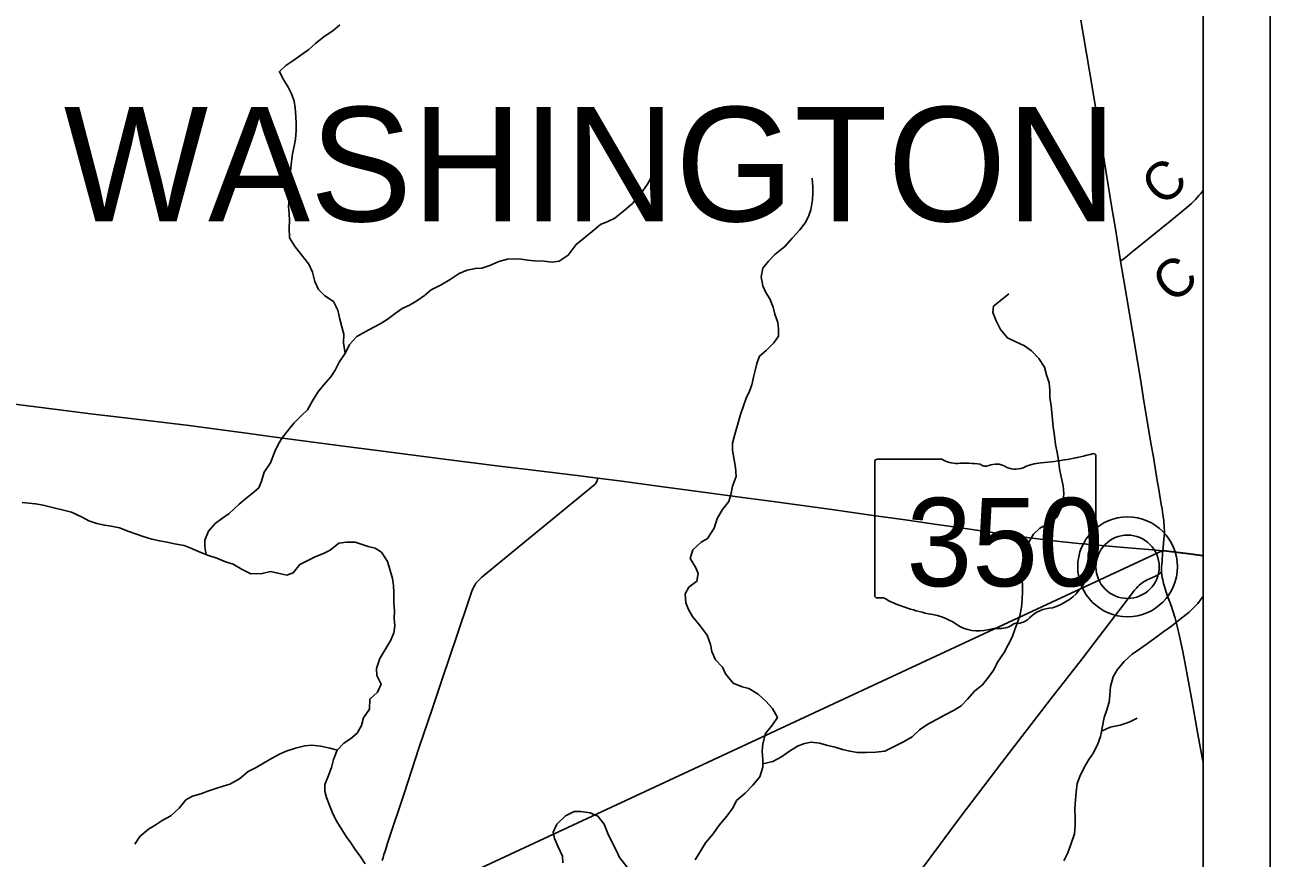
# Model space of a CAD drawing. Extents: x 0 to 34, y 0 to 22.
# Drawn here: x 7.143 to 9, y 16.125 to 17.368 of the extents above; entities that cross this region are included whole.
import ezdxf

# ---------------------------------------------------------------- set-up
doc = ezdxf.new("R2010")
doc.units = 0
for name, color, linetype in [('GM_X_County_Road', 7, 'Continuous'), ('GM_X_County_Road_Text', 7, 'Continuous'), ('GM_X_Minor_River', 7, 'Continuous'), ('GM_X_State_Location', 7, 'Continuous'), ('GM_X_State_Route', 7, 'Continuous'), ('GM_X_State_Shield', 7, 'Continuous'), ('GM_X_Township_Road', 7, 'Continuous'), ('GM_X_Township_Text', 7, 'Continuous'), ('GM_X_Unincorporated', 7, 'Continuous'), ('GM_X_Unincorporated_Location', 7, 'Continuous'), ('SH_Data', 7, 'Continuous')]:
    doc.layers.add(name, color=color, linetype=linetype)

msp = doc.modelspace()

# ---------------------------------------------------------------- linework, layer by layer
at = {"layer": 'GM_X_County_Road'}
for points in [[(8.7771, 17.0151), (8.7843, 17.021), (8.7939, 17.0288), (8.8503, 17.0747), (8.8759, 17.0954), (8.8828, 17.1015), (8.8858, 17.1044), (8.8886, 17.1071), (8.8912, 17.1101), (8.8939, 17.1131), (8.8961, 17.1159), (8.8985, 17.1189), (8.9, 17.121)], [(8.4696, 16.0943), (8.5071, 16.1446), (8.5308, 16.1765), (8.5465, 16.1973), (8.6, 16.2675), (8.673, 16.3626), (8.7196, 16.4224), (8.745, 16.4554), (8.7808, 16.5023), (8.7963, 16.5225), (8.798, 16.5245), (8.8007, 16.5276), (8.8028, 16.53), (8.805, 16.532), (8.8068, 16.5335), (8.8087, 16.5351), (8.8105, 16.5364), (8.8122, 16.5375), (8.8143, 16.5388), (8.8165, 16.5399), (8.8282, 16.545), (8.831, 16.5464), (8.8334, 16.548), (8.8383, 16.5513)]]:
    msp.add_lwpolyline(points, dxfattribs=at)
at = {"layer": 'GM_X_Minor_River'}
for points in [[(7.6207, 16.8777), (7.6184, 16.8933), (7.619, 16.9066), (7.6161, 16.9172), (7.6132, 16.929), (7.6099, 16.942), (7.6033, 16.955), (7.5905, 16.9635), (7.5811, 16.9731), (7.5759, 16.9849), (7.572, 16.999), (7.5668, 17.0109), (7.5556, 17.025), (7.5463, 17.0369), (7.5377, 17.0503), (7.5375, 17.0651), (7.538, 17.0754), (7.5374, 17.0864), (7.5364, 17.0963), (7.5374, 17.1099), (7.5387, 17.1266), (7.5393, 17.1399), (7.5394, 17.1498), (7.5408, 17.1642), (7.5424, 17.1752), (7.5449, 17.1869), (7.5469, 17.1975), (7.5478, 17.2104), (7.548, 17.2206), (7.5474, 17.2309), (7.5464, 17.2438), (7.545, 17.2541), (7.5413, 17.264), (7.5358, 17.2747), (7.5276, 17.2889), (7.5228, 17.2984), (7.5324, 17.307), (7.5428, 17.3141), (7.5547, 17.3227), (7.5669, 17.3312), (7.5766, 17.3398), (7.5896, 17.3503), (7.6026, 17.3589), (7.613, 17.3678)], [(7.4138, 16.5776), (7.4115, 16.5892), (7.4116, 16.5991), (7.4171, 16.6127), (7.4271, 16.6243), (7.4367, 16.631), (7.4482, 16.6392), (7.4628, 16.6531), (7.4724, 16.6609), (7.4824, 16.6688), (7.492, 16.6774), (7.4964, 16.6872), (7.5003, 16.7004), (7.5096, 16.7144), (7.5163, 16.7314), (7.521, 16.7419), (7.5268, 16.7517), (7.5365, 16.7638), (7.545, 16.7743), (7.5554, 16.7848), (7.565, 16.7934), (7.572, 16.8069), (7.5802, 16.8197), (7.5887, 16.8306), (7.5995, 16.843), (7.6061, 16.8528), (7.6119, 16.8645), (7.6212, 16.8784), (7.6275, 16.8909), (7.6383, 16.9029), (7.6505, 16.9099), (7.6635, 16.917), (7.6731, 16.9218), (7.6834, 16.9281), (7.6957, 16.9371), (7.7057, 16.9445), (7.7168, 16.9497), (7.7279, 16.956), (7.7394, 16.9642), (7.7494, 16.9724), (7.7643, 16.9798), (7.7773, 16.988), (7.7911, 16.9969), (7.8029, 17.0021), (7.8151, 17.0046), (7.8246, 17.0049), (7.8365, 17.0089), (7.8498, 17.0148), (7.8632, 17.0184), (7.8734, 17.019), (7.8833, 17.0182), (7.8935, 17.0169), (7.903, 17.016), (7.9174, 17.0151), (7.9296, 17.0138), (7.9399, 17.0155), (7.9533, 17.0245), (7.9653, 17.0402), (7.9756, 17.0488), (7.9891, 17.0597), (8.0017, 17.0698), (8.0128, 17.0746), (8.0228, 17.0794), (8.0366, 17.0902), (8.0493, 17.1014), (8.0612, 17.1153), (8.0717, 17.13), (8.0794, 17.1435)], [(8.1502, 16.4715), (8.1386, 16.4853), (8.1326, 16.496), (8.129, 16.5059), (8.128, 16.5192), (8.1335, 16.529), (8.1454, 16.538), (8.1474, 16.5493), (8.1434, 16.5589), (8.1352, 16.5719), (8.1395, 16.5847), (8.1515, 16.596), (8.161, 16.6019), (8.1711, 16.617), (8.1755, 16.6317), (8.1836, 16.6449), (8.1929, 16.6569), (8.1961, 16.6668), (8.1985, 16.6796), (8.2037, 16.694), (8.2031, 16.7077), (8.201, 16.7191), (8.1985, 16.7335), (8.1983, 16.7438), (8.2023, 16.7589), (8.207, 16.7741), (8.2102, 16.7865), (8.2142, 16.7983), (8.2189, 16.8111), (8.2236, 16.8213), (8.2275, 16.8311), (8.23, 16.8421), (8.232, 16.8523), (8.2348, 16.8629), (8.2388, 16.8735), (8.2484, 16.8821), (8.2603, 16.8933), (8.2669, 16.9035), (8.267, 16.9145), (8.266, 16.924), (8.2616, 16.9362), (8.2591, 16.9465), (8.254, 16.9591), (8.248, 16.9686), (8.2436, 16.9786), (8.2411, 16.9919), (8.2436, 17.0048), (8.2521, 17.0153), (8.2617, 17.0254), (8.2767, 17.037), (8.2875, 17.0497), (8.2986, 17.0621), (8.3068, 17.0723), (8.3118, 17.0821), (8.3154, 17.0919), (8.3175, 17.1067), (8.3184, 17.1169), (8.3181, 17.1264), (8.3172, 17.1393)], [(8.2439, 16.2657), (8.2587, 16.2693), (8.2717, 16.2759), (8.2836, 16.2845), (8.2955, 16.292), (8.3058, 16.296), (8.3157, 16.2981), (8.3282, 16.2965), (8.3407, 16.2929), (8.3517, 16.2905), (8.3627, 16.2869), (8.3733, 16.2845), (8.3846, 16.2824), (8.3979, 16.2827), (8.412, 16.2829), (8.4257, 16.2846), (8.4387, 16.2909), (8.4532, 16.2983), (8.4662, 16.3061), (8.4774, 16.3165), (8.4896, 16.3247), (8.5026, 16.3318), (8.5145, 16.3381), (8.529, 16.3459), (8.5394, 16.3522), (8.5486, 16.3619), (8.5598, 16.3747), (8.571, 16.3837), (8.5802, 16.3949), (8.588, 16.4058), (8.5938, 16.4172), (8.6035, 16.4318), (8.6152, 16.4545), (8.6195, 16.4658), (8.6231, 16.4756), (8.6267, 16.4866), (8.6295, 16.4991), (8.6304, 16.5104), (8.631, 16.5237), (8.6307, 16.5332), (8.6297, 16.5427), (8.6298, 16.5541), (8.6304, 16.564), (8.6336, 16.5783), (8.6387, 16.5938), (8.6473, 16.6082), (8.6569, 16.6171), (8.6707, 16.6246), (8.6826, 16.6339), (8.6892, 16.6479), (8.6916, 16.6584), (8.6925, 16.6687), (8.6915, 16.6801), (8.6887, 16.6938), (8.6862, 16.7056), (8.6845, 16.7185), (8.6823, 16.7299), (8.6802, 16.7421), (8.6785, 16.7547), (8.6768, 16.7683), (8.6758, 16.7786), (8.6748, 16.7892), (8.6734, 16.7999), (8.6717, 16.8117), (8.6714, 16.8227), (8.6704, 16.8337), (8.6668, 16.8459), (8.6635, 16.857), (8.6554, 16.8704), (8.6445, 16.8815), (8.634, 16.8889), (8.6208, 16.8951), (8.6083, 16.901), (8.5978, 16.9132), (8.5916, 16.9262), (8.5864, 16.9388), (8.5877, 16.9483), (8.5973, 16.9561), (8.6103, 16.9666)], [(7.5203, 16.5502), (7.5097, 16.5523), (7.4972, 16.5494), (7.4804, 16.5492), (7.4672, 16.5555), (7.454, 16.5636), (7.4427, 16.5668), (7.4295, 16.5723), (7.4174, 16.5763), (7.403, 16.5818), (7.3932, 16.5861), (7.3811, 16.5915), (7.3667, 16.5936), (7.3554, 16.5964), (7.344, 16.5981), (7.3326, 16.6005), (7.3198, 16.6045), (7.3099, 16.6084), (7.2982, 16.6123), (7.2846, 16.6174), (7.2721, 16.6199), (7.2619, 16.6215), (7.2509, 16.624), (7.2388, 16.6283), (7.2286, 16.6337), (7.2131, 16.6408), (7.1991, 16.6444), (7.1866, 16.6476), (7.1707, 16.6512), (7.159, 16.6536), (7.1495, 16.6545), (7.1393, 16.6554)], [(7.6505, 16.1166), (7.6442, 16.1265), (7.636, 16.138), (7.6296, 16.1476), (7.6225, 16.1572), (7.6136, 16.1717), (7.6077, 16.1813), (7.6021, 16.1924), (7.5981, 16.2023), (7.5933, 16.2153), (7.5908, 16.2248), (7.5905, 16.235), (7.5949, 16.246), (7.6004, 16.26), (7.6036, 16.2721), (7.6091, 16.286), (7.6191, 16.2965), (7.6287, 16.3029), (7.639, 16.3115), (7.6453, 16.3228), (7.6485, 16.3341), (7.6574, 16.3473), (7.6576, 16.3621), (7.6691, 16.3726), (7.6746, 16.3846), (7.6683, 16.3976), (7.6677, 16.4079), (7.6724, 16.4226), (7.6814, 16.4377), (7.6888, 16.4501), (7.6935, 16.4611), (7.6951, 16.4717), (7.6941, 16.4823), (7.6943, 16.4937), (7.6933, 16.5059), (7.6935, 16.5211), (7.6929, 16.5317), (7.6915, 16.542), (7.6868, 16.5576), (7.6839, 16.5675), (7.6753, 16.5813), (7.6655, 16.5871), (7.6553, 16.5899), (7.6357, 16.5962), (7.6227, 16.596), (7.6117, 16.5946), (7.5987, 16.5845), (7.5887, 16.5794), (7.5773, 16.5749), (7.5631, 16.5679), (7.5532, 16.5627), (7.5435, 16.5507), (7.534, 16.547), (7.5203, 16.5502)], [(8.6924, 16.1209), (8.6982, 16.133), (8.7034, 16.147), (8.7085, 16.1613), (8.7094, 16.1742), (8.7092, 16.1845), (8.709, 16.1985), (8.7099, 16.2118), (8.7108, 16.2232), (8.7125, 16.2364), (8.7165, 16.247), (8.7227, 16.2602), (8.7297, 16.2719), (8.7367, 16.2821), (8.743, 16.2953), (8.7469, 16.3066), (8.7526, 16.3346), (8.7566, 16.3463), (8.7601, 16.3577), (8.761, 16.3679), (8.762, 16.3812), (8.766, 16.3956), (8.7718, 16.4057), (8.7826, 16.4181), (8.7941, 16.4294), (8.8053, 16.4368), (8.8171, 16.445), (8.8283, 16.4532), (8.8417, 16.4629), (8.8532, 16.4711), (8.8659, 16.4812), (8.8793, 16.4916), (8.8924, 16.5048), (8.9, 16.5155)], [(8.1428, 16.1224), (8.1506, 16.1355), (8.1583, 16.1476), (8.1695, 16.1611), (8.1788, 16.1743), (8.19, 16.1874), (8.1993, 16.2006), (8.2044, 16.2108), (8.2171, 16.222), (8.229, 16.234), (8.239, 16.2464), (8.2438, 16.2607), (8.2439, 16.2714), (8.2426, 16.2847), (8.2439, 16.2953), (8.2475, 16.3108), (8.2583, 16.3239), (8.2657, 16.3349), (8.2579, 16.3482), (8.2482, 16.359), (8.2369, 16.3694), (8.223, 16.3779), (8.2131, 16.3803), (8.1995, 16.3862), (8.1879, 16.4), (8.1835, 16.4099), (8.173, 16.4207), (8.1675, 16.4333), (8.1657, 16.4436), (8.1606, 16.4573), (8.1502, 16.4715)], [(8.7485, 16.3143), (8.7615, 16.3205), (8.7764, 16.3233), (8.7901, 16.3277), (8.8016, 16.334)], [(7.6093, 16.2862), (7.5981, 16.2892), (7.5848, 16.292), (7.5712, 16.2937), (7.5609, 16.2927), (7.5468, 16.2891), (7.5331, 16.2844), (7.5232, 16.2799), (7.5113, 16.2736), (7.4994, 16.2666), (7.4883, 16.2603), (7.4761, 16.254), (7.4634, 16.2431), (7.4489, 16.2353), (7.439, 16.2324), (7.4294, 16.2295), (7.4161, 16.2251), (7.4058, 16.2211), (7.3932, 16.2175), (7.3836, 16.2119), (7.3736, 16.1995), (7.3609, 16.1883), (7.3479, 16.1812), (7.3375, 16.1742), (7.3276, 16.1682), (7.3149, 16.1574), (7.3071, 16.1457)], [(8.0412, 16.1115), (8.03, 16.1261), (8.0256, 16.136), (8.0178, 16.1502), (8.0127, 16.1616), (8.0072, 16.1757), (7.9978, 16.1876), (7.9861, 16.1927), (7.9725, 16.1944), (7.9626, 16.1945), (7.9496, 16.1882), (7.9365, 16.1759), (7.931, 16.1638), (7.9332, 16.1543), (7.9387, 16.1421), (7.945, 16.1279), (7.9456, 16.1181)]]:
    msp.add_lwpolyline(points, dxfattribs=at)
at = {"layer": 'GM_X_State_Route'}
for points in [[(8.8401, 16.5833), (8.8423, 16.6056), (8.8424, 16.6098), (8.8424, 16.6136), (8.8423, 16.6176), (8.8422, 16.621), (8.8418, 16.6254), (8.8414, 16.629), (8.8408, 16.6338), (8.8402, 16.6378), (8.8397, 16.6412), (8.8389, 16.6458), (8.8378, 16.6524), (8.834, 16.6749), (8.8316, 16.6884), (8.8255, 16.7258), (8.8223, 16.7441), (8.8162, 16.7803), (8.8119, 16.8067), (8.8076, 16.833), (8.7991, 16.8839), (8.7815, 16.9893), (8.7771, 17.0151), (8.7765, 17.0187), (8.7693, 17.0634), (8.7632, 17.1008), (8.7532, 17.1628), (8.7433, 17.2241), (8.7345, 17.2755), (8.7178, 17.3748)], [(7.1163, 16.8033), (7.1909, 16.7939), (7.2143, 16.7911), (7.2451, 16.7873), (7.2717, 16.7841), (7.3303, 16.777), (7.3883, 16.77), (7.4104, 16.7671), (7.4739, 16.7588), (7.5164, 16.753), (7.6186, 16.7393), (7.6691, 16.7328), (7.7683, 16.7198), (7.851, 16.7098), (7.8972, 16.7041), (7.9706, 16.695), (7.9976, 16.6917), (8.0014, 16.6912), (8.0335, 16.6872), (8.0913, 16.6793), (8.1474, 16.672), (8.2207, 16.662), (8.2515, 16.6581), (8.35, 16.6445), (8.4047, 16.6365), (8.4558, 16.6294), (8.5068, 16.622), (8.532, 16.6184), (8.596, 16.6092), (8.6378, 16.6032), (8.6692, 16.5991), (8.6908, 16.5967), (8.7143, 16.5945), (8.7329, 16.5926), (8.7484, 16.5915), (8.7824, 16.5885), (8.8245, 16.5848), (8.8401, 16.5833)], [(8.9, 16.2678), (8.8996, 16.2702), (8.8989, 16.2743), (8.8982, 16.2778), (8.8922, 16.3097), (8.8839, 16.3581), (8.8761, 16.4015), (8.8699, 16.4332), (8.8649, 16.4562), (8.8614, 16.4711), (8.8605, 16.4749), (8.8595, 16.4789), (8.8584, 16.4827), (8.8569, 16.4876), (8.8559, 16.491), (8.8545, 16.4952), (8.8528, 16.5004), (8.8467, 16.5174), (8.8447, 16.5234), (8.8431, 16.5286), (8.8421, 16.5316), (8.8413, 16.5345), (8.8407, 16.537), (8.8399, 16.5404), (8.8392, 16.5437), (8.8388, 16.546), (8.8385, 16.5481), (8.8383, 16.5513), (8.8382, 16.5531), (8.8383, 16.5563), (8.8383, 16.5594), (8.8386, 16.5635), (8.8389, 16.5681), (8.8398, 16.5796), (8.8401, 16.5833)], [(8.8401, 16.5833), (8.8449, 16.5829), (8.8819, 16.5783), (8.8997, 16.5759), (8.9, 16.5758)]]:
    msp.add_lwpolyline(points, dxfattribs=at)
at = {"layer": 'GM_X_State_Shield'}
for p, q in [((8.4108, 16.7165), (8.4108, 16.5164)), ((8.5106, 16.72), (8.4141, 16.72)), ((8.7404, 16.6203), (8.7404, 16.7249)), ((8.7404, 16.6203), (8.7404, 16.6203))]:
    msp.add_line(p, q, dxfattribs=at)
for centre, major_axis, start_param, end_param in [((8.623, 16.9928), (0.3495, 0), 4.814394, 5.042369), ((8.7367, 16.7254), (0.00367, 0), 6.141152, 7.989035), ((8.4146, 16.717), (0.00382, 0), 1.712693, 3.28349), ((8.5336, 16.7432), (0.037, 0), 4.042523, 4.731795), ((8.5458, 16.6076), (0.133, 0), 1.404758, 1.657858), ((8.576, 16.718), (0.0107, 0), 3.836095, 5.185415), ((8.5917, 16.6949), (0.0222, 0), 0.950623, 2.079405), ((8.6204, 16.7266), (0.0267, 0), 4.081561, 5.145723), ((8.6676, 16.6589), (0.0703, 0), 1.699011, 2.107814), ((8.7395, 16.6126), (0.00568, 0), 1.883978, 3.671073), ((8.7365, 16.6199), (0.00393, 0), 5.05454, 6.418171), ((8.7034, 16.5993), (0.0341, 0), 5.934695, 6.695948), ((8.7535, 16.5765), (0.0248, 0), 2.387724, 3.262537), ((8.6426, 16.5631), (0.0874, 0), 5.101752, 6.440018), ((8.4146, 16.516), (0.00385, 0), 3.00124, 4.508301), ((8.4152, 16.5365), (0.0294, 0), 4.665946, 4.897461), ((8.4212, 16.5049), (0.0106, 0), 0.519207, 1.627899), ((8.555, 16.6847), (0.2524, 0), 4.195997, 4.488961), ((8.4798, 16.4265), (0.079, 0), 0.823519, 1.323587), ((8.6794, 16.4602), (0.0479, 0), 1.647645, 2.488434), ((8.5652, 16.5039), (0.0501, 0), 4.026481, 4.996735), ((8.5942, 16.4347), (0.0412, 0), 1.495662, 1.94098), ((8.5978, 16.4889), (0.0267, 0), 4.691044, 5.507374), ((8.622, 16.4695), (0.00752, 0), 1.147584, 2.315152), ((8.6188, 16.497), (0.0282, 0), 4.937069, 5.64225)]:
    msp.add_ellipse(centre, major_axis=major_axis, ratio=0.8, start_param=start_param, end_param=end_param, dxfattribs=at)
at = {"layer": 'GM_X_Township_Road'}
for points in [[(3.7277, 16.7873), (3.6691, 16.5264), (3.3385, 15.3189), (3.2153, 14.8228), (3.0598, 14.2522), (3.3693, 14.1947), (3.882, 14.1), (5.5061, 14.1), (5.6307, 14.246), (5.7089, 14.3412), (6.2381, 14.9624), (6.7874, 15.6255), (6.8121, 15.6375), (7.6646, 16.0363), (8.8399, 16.5839), (8.8447, 16.5834), (8.8816, 16.5789), (8.8995, 16.5764), (8.9, 16.5763), (8.9, 19.1426)], [(7.6759, 16.1215), (7.6774, 16.126), (7.6788, 16.1304), (7.6809, 16.1368), (7.6842, 16.1474), (7.6852, 16.1504), (7.7088, 16.2216), (7.7314, 16.2906), (7.751, 16.3489), (7.7674, 16.3978), (7.7753, 16.4214), (7.7892, 16.4626), (7.8032, 16.5038), (7.8048, 16.5085), (7.8099, 16.5232), (7.8113, 16.5267), (7.8127, 16.5296), (7.8142, 16.5323), (7.816, 16.535), (7.8184, 16.5378), (7.821, 16.5406), (7.8241, 16.5434), (7.8276, 16.5465), (7.8502, 16.565), (7.8997, 16.6056), (7.927, 16.6281), (7.9936, 16.6827), (7.9949, 16.6841), (7.9958, 16.6857), (7.9965, 16.6883), (7.9976, 16.6917)]]:
    msp.add_lwpolyline(points, dxfattribs=at)
msp.add_lwpolyline([(5.5061, 14.1), (8.9, 14.1), (8.9, 16.5763), (8.8995, 16.5764), (8.8816, 16.5789), (8.8447, 16.5834), (8.8399, 16.5839), (7.6646, 16.0363), (6.8121, 15.6375), (6.7874, 15.6255), (6.2381, 14.9624), (5.7089, 14.3412), (5.6307, 14.246)], close=True, dxfattribs=at)
at = {"layer": 'GM_X_Unincorporated'}
for radius in [0.0744, 0.0472]:
    msp.add_circle((8.7875, 16.5595), radius, dxfattribs=at)
at = {"layer": 'GM_X_Unincorporated_Location'}
msp.add_line((8.7875, 16.5595), (8.7875, 16.5595), dxfattribs=at)
at = {"layer": 'SH_Data'}
for p, q in [((9, 21), (9, 14)), ((8.9, 20.9), (8.9, 14.1))]:
    msp.add_line(p, q, dxfattribs=at)

# ---------------------------------------------------------------- texts
at = {"layer": 'GM_X_County_Road_Text'}
for rotation, p in [(41.1195, (8.8396, 17.0951)), (39.4772, (8.8544, 16.9504))]:
    msp.add_text('C', height=0.0568, rotation=rotation, dxfattribs=at).set_placement(p)
at = {"layer": 'GM_X_State_Location'}
for s in ['s', 'r']:
    msp.add_text(s, height=0.000189, dxfattribs=at).set_placement((8.5719, 16.6032))
msp.add_text('350', height=0.000189, rotation=0, dxfattribs=at).set_placement((8.505, 16.5894))
at = {"layer": 'GM_X_State_Shield'}
msp.add_text('350', height=0.13184, dxfattribs=at).set_placement((8.4578, 16.5305))
at = {"layer": 'GM_X_Township_Text'}
msp.add_text('WASHINGTON', height=0.17045, rotation=0, dxfattribs=at).set_placement((7.2014, 17.0748))

doc.saveas('drawing.dxf')
